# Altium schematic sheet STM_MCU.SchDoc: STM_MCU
size A3; Author: J. Garnier; DrawnBy: J. Garnier; SheetNumber: 2; SheetTotal: 8
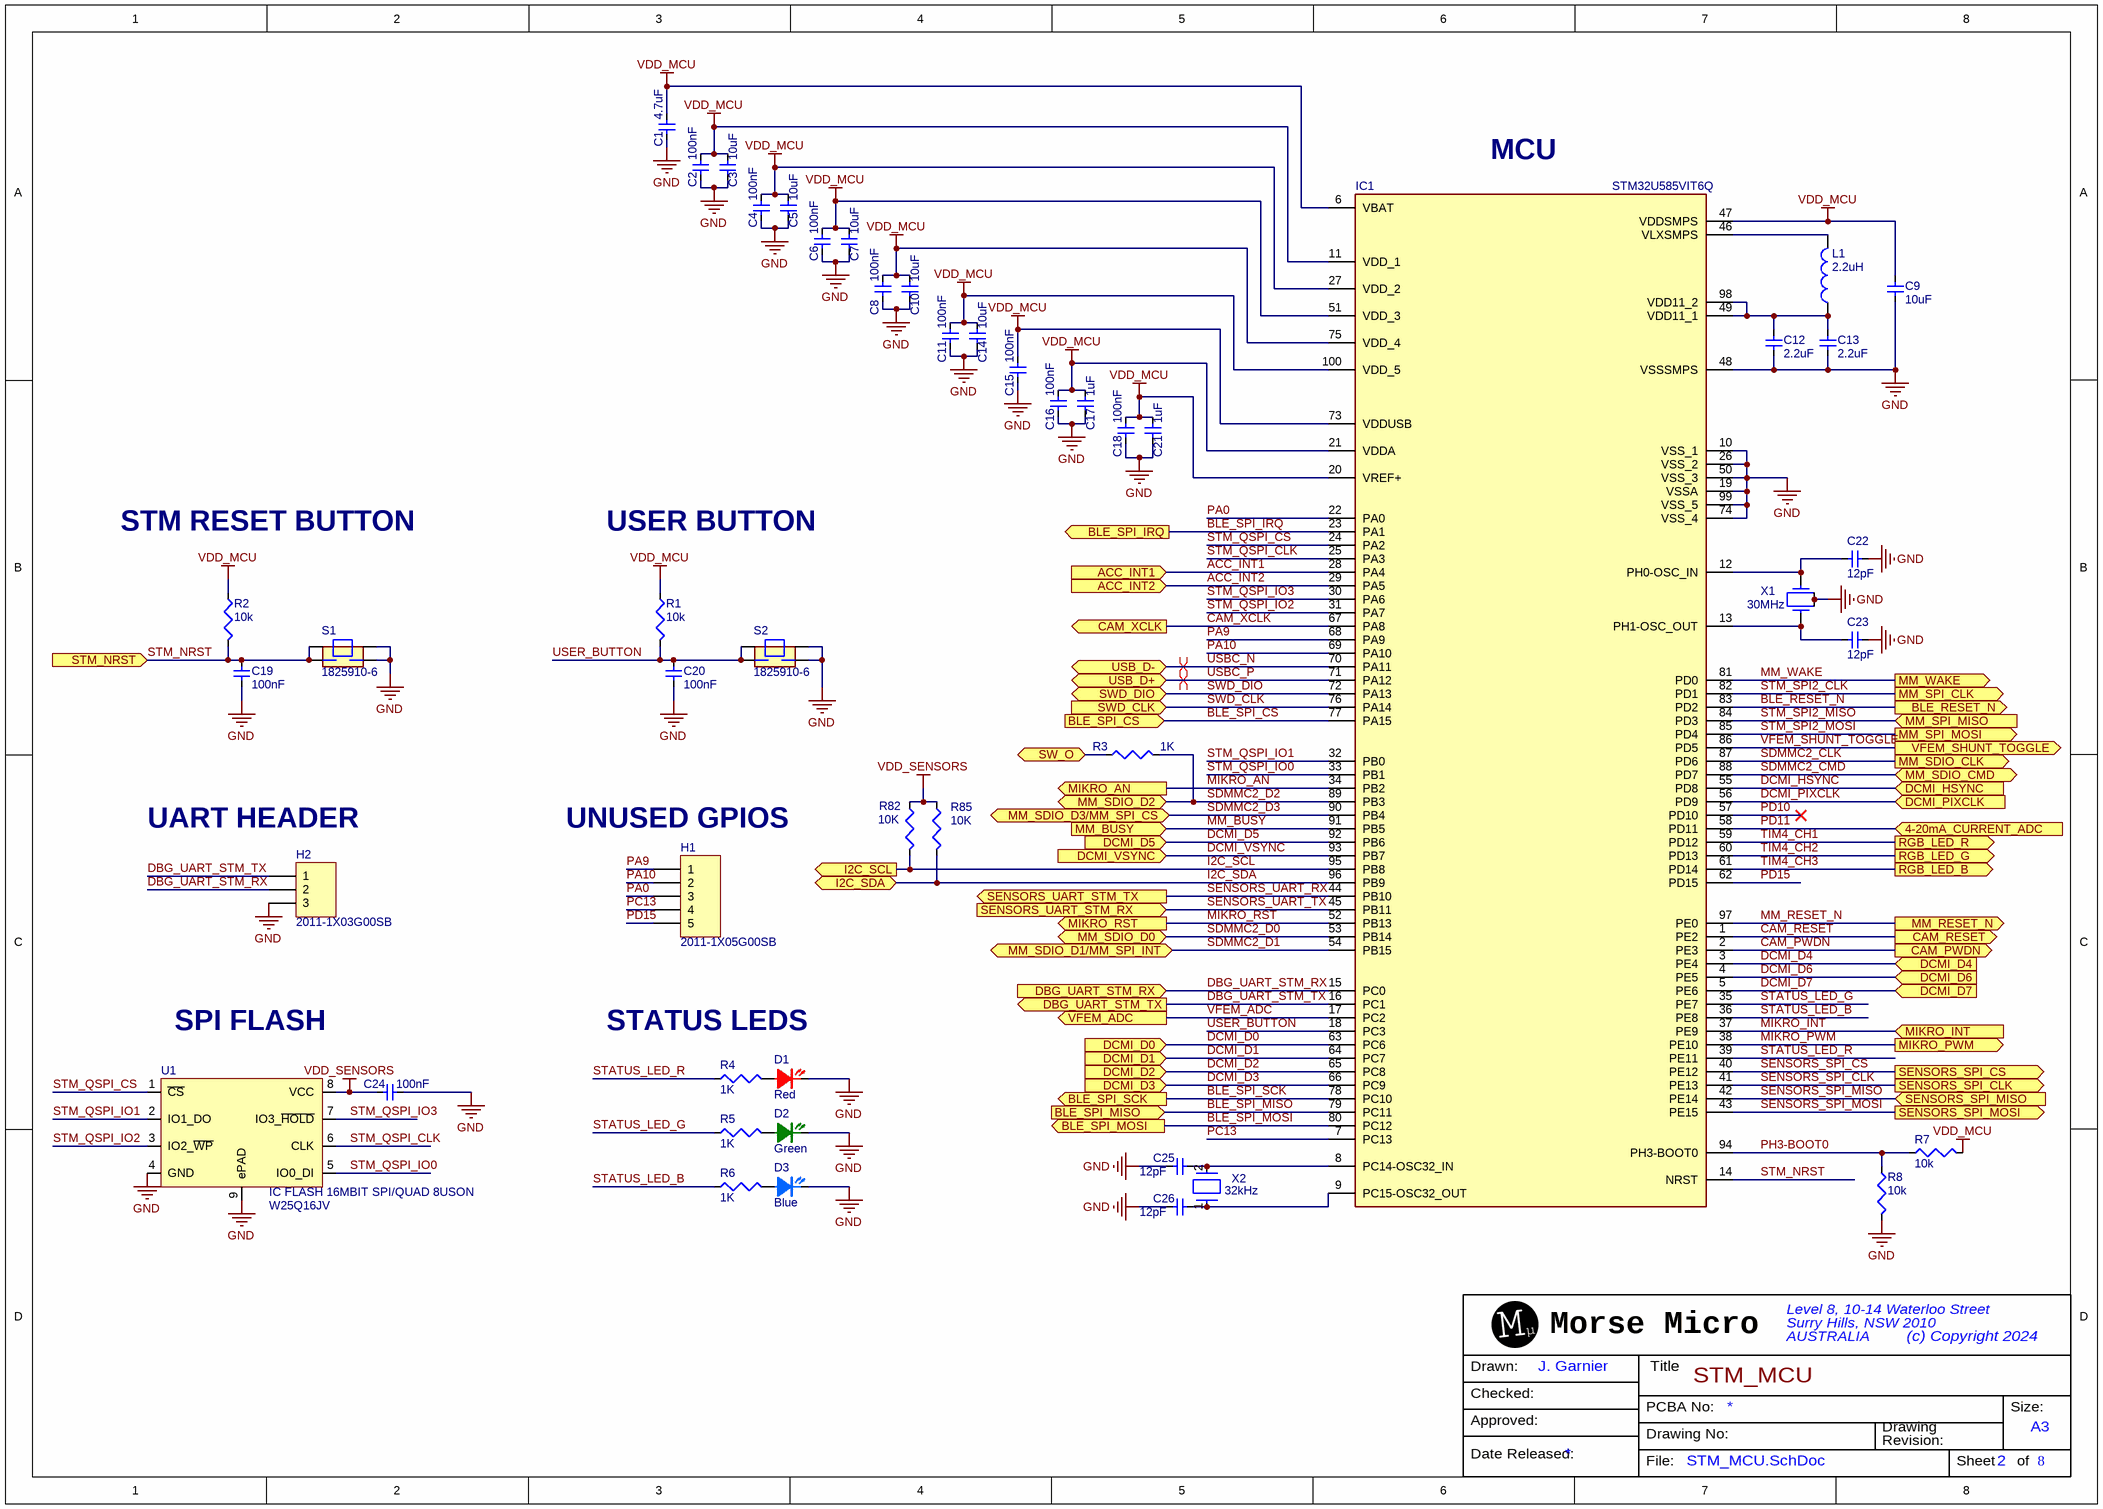
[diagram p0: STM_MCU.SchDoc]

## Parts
C1  value 4.7uF  [0402_cap]  (hidden comment: GRM155R61A475MEAAD)
C2  value 100nF  [0402_cap]  (hidden comment: C1005X7R1H104K050BE)
C3  value 10uF  [0402_cap]  (hidden comment: CL05A106MP8NUB8)
C4  value 100nF  [0402_cap]  (hidden comment: C1005X7R1H104K050BE)
C5  value 10uF  [0402_cap]  (hidden comment: CL05A106MP8NUB8)
C6  value 100nF  [0402_cap]  (hidden comment: C1005X7R1H104K050BE)
C7  value 10uF  [0402_cap]  (hidden comment: CL05A106MP8NUB8)
C8  value 100nF  [0402_cap]  (hidden comment: C1005X7R1H104K050BE)
C9  value 10uF  [0402_cap]  (hidden comment: CL05A106MP8NUB8)
C10  value 10uF  [0402_cap]  (hidden comment: CL05A106MP8NUB8)
C11  value 100nF  [0402_cap]  (hidden comment: C1005X7R1H104K050BE)
C12  value 2.2uF  [CAPC1005X06N]  (hidden comment: GRM155R61E225ME15D)
C13  value 2.2uF  [CAPC1005X06N]  (hidden comment: GRM155R61E225ME15D)
C14  value 10uF  [0402_cap]  (hidden comment: CL05A106MP8NUB8)
C15  value 100nF  [0402_cap]  (hidden comment: C1005X7R1H104K050BE)
C16  value 100nF  [0402_cap]  (hidden comment: C1005X7R1H104K050BE)
C17  value 1uF  [CAPC1005X06N]  (hidden comment: CL05A105KA5NQNC)
C18  value 100nF  [0402_cap]  (hidden comment: C1005X7R1H104K050BE)
C19  value 100nF  [CAPC1005X06N]  (hidden comment: LMK105BJ104KV-F)
C20  value 100nF  [CAPC1005X06N]  (hidden comment: LMK105BJ104KV-F)
C21  value 1uF  [CAPC1005X06N]  (hidden comment: CL05A105KA5NQNC)
C22  value 12pF  [CAPC0603X03N]  (hidden comment: GRM0335C1E120JA01D)
C23  value 12pF  [CAPC0603X03N]  (hidden comment: GRM0335C1E120JA01D)
C24  value 100nF  [CAPC0603X03N]  (hidden comment: CL03A104KQ3NNNC)
C25  value 12pF  [CAPC0603X03N]  (hidden comment: GRM0335C1E120JA01D)
C26  value 12pF  [CAPC0603X03N]  (hidden comment: GRM0335C1E120JA01D)
D1  value Red  [LED_0805_RED]  (hidden comment: LTST-C170KRKT)
D2  value Green  [LED_0805_GREEN]  (hidden comment: LTST-C170KGKT)
D3  value Blue  [LED_0805_BLUE]  (hidden comment: LTST-C170TBKT)
H1  2011-1X05G00SB  [HDR1X5 - Short Gold]
H2  2011-1X03G00SB  [HDR1X3]
IC1  STM32U585VIT6Q  [STM32U585VIT6]
L1  value 2.2uH  [INDC1608X10N]  (hidden comment: ASMPH-0603-2R2M-T)
R1  value 10k  [RESC1005X04N]  (hidden comment: MCR01MZPF1002)
R2  value 10k  [RESC1005X04N]  (hidden comment: MCR01MZPF1002)
R3  value 1K  [RESC1005X04N]  (hidden comment: ERJ-2RKF1001X)
R4  value 1K  [RESC1005X04N]  (hidden comment: ERJ-2RKF1001X)
R5  value 1K  [RESC1005X04N]  (hidden comment: ERJ-2RKF1001X)
R6  value 1K  [RESC1005X04N]  (hidden comment: ERJ-2RKF1001X)
R7  value 10k  [RESC1005X04N]  (hidden comment: MCR01MZPF1002)
R8  value 10k  [RESC1005X04N]  (hidden comment: MCR01MZPF1002)
R82  value 10K  [0402_res]  (hidden comment: ERJ-2RKF1002X)
R85  value 10K  [0402_res]  (hidden comment: ERJ-2RKF1002X)
S1  1825910-6  [TL1105]
S2  1825910-6  [TL1105]
U1  IC FLASH 16MBIT SPI/QUAD 8USON  value W25Q16JV  [USON8P20X30X6]
X1  value 30MHz  [XTAL_SMD_2016]  (hidden comment: ECS-300-10-37-CKM-TR)
X2  value 32kHz  [FP-ABS06-MFG]  (hidden comment: ABS06-107-32.768KHZ-T)

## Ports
4-20mA_CURRENT_ADC (in, see Main[3C], Sensors[7A]), ACC_INT1 (in, see Main[3C], Sensors[1B]), ACC_INT2 (in, see Main[3C], Sensors[1B]), BLE_RESET_N (out, see Main[2C], BLE_Module[2B]), BLE_SPI_CS (in, see Main[2C], BLE_Module[4B]), BLE_SPI_IRQ (out, see Main[2C], BLE_Module[4B]), BLE_SPI_MISO (in, see Main[2C], BLE_Module[4B]), BLE_SPI_MOSI (out, see Main[2C], BLE_Module[4B]), BLE_SPI_SCK (out, see Main[2C], BLE_Module[4A]), CAM_PWDN (out, see Main[3B], Sensors[7C]), CAM_RESET (out, see Main[3B], Sensors[5C]), CAM_XCLK (out, see Main[3B], Sensors[7C]), DBG_UART_STM_RX (in, see Main[2B]), DBG_UART_STM_TX (out, see Main[2B]), DCMI_D0 (in, see Main[3B]), DCMI_D1 (in, see Main[3B]), DCMI_D2 (in, see Main[3B]), DCMI_D3 (in, see Main[3C]), DCMI_D4 (in, see Main[3C]), DCMI_D5 (in, see Main[3C]), DCMI_D6 (in, see Main[3C]), DCMI_D7 (in, see Main[3C]), DCMI_HSYNC (in, see Main[3B]), DCMI_PIXCLK (in, see Main[3B]), DCMI_VSYNC (in, see Main[3B]), I2C_SCL (out, see Main[3A], Sensors[4A]), I2C_SDA (bidir, see Main[3A], Sensors[4A]), MIKRO_AN (out, see Main[3B], Sensors[5C]), MIKRO_INT (in, see Main[3B], Sensors[8C]), MIKRO_PWM (out, see Main[3A], Sensors[8C]), MIKRO_RST (out, see Main[3B], Sensors[5C]), MM_BUSY (in, see Main[2A], HaLow_Module[2A]), MM_RESET_N (out, see Main[2A], HaLow_Module[2B]), MM_SDIO_CLK (out, see Main[2A], HaLow_Module[1C]), MM_SDIO_CMD (bidir, see Main[2A], HaLow_Module[1C]), MM_SDIO_D0 (bidir, see Main[2A], HaLow_Module[1C]), MM_SDIO_D1/MM_SPI_INT (bidir, see Main[2A], HaLow_Module[1B]), MM_SDIO_D2 (bidir, see Main[2B], HaLow_Module[1B]), MM_SDIO_D3/MM_SPI_CS (bidir, see Main[2B], HaLow_Module[1B]), MM_SPI_CLK (out, see Main[2B], HaLow_Module[3C]), MM_SPI_MISO (in, see Main[2B], HaLow_Module[3C]), MM_SPI_MOSI (out, see Main[2B], HaLow_Module[3C]), MM_WAKE (out, see Main[2A], HaLow_Module[2B]), RGB_LED_B (out, see Main[3A], Sensors[2D]), RGB_LED_G (out, see Main[3A], Sensors[2D]), RGB_LED_R (out, see Main[3A], Sensors[3D]), SENSORS_SPI_CLK (out, see Main[3B]), SENSORS_SPI_CS (out, see Main[3B], Sensors[5C]), SENSORS_SPI_MISO (in, see Main[3B], Sensors[5D]), SENSORS_SPI_MOSI (out, see Main[3B], Sensors[5D]), SENSORS_UART_STM_RX (in, see Main[3B]), SENSORS_UART_STM_TX (out, see Main[3B]), STM_NRST (in, see Main[2B], Power[1B]), SW_O (bidir, see Main[2B], Power[1B]), SWD_CLK (in, see Main[2B], Power[1B]), SWD_DIO (bidir, see Main[2B], Power[1B]), USB_D+ (bidir, see Main[2B], Power[4A]), USB_D- (bidir, see Main[2B], Power[4A]), VFEM_ADC (out, see Main[2B], Power[5D]), VFEM_SHUNT_TOGGLE (out, see Main[2C], Power[4D])

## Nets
GND: C1.1 C2.1 C3.1 C4.1 C5.1 C6.1 C7.1 C8.1 C9.2 C10.1 C11.1 C12.2 C13.2 C14.1 C15.1 C16.1 C17.1 C18.1 C19.2 C20.2 C21.1 C22.2 C23.2 C24.1 C25.1 C26.1 D1.K D2.K D3.K H2.3 IC1.10(VSS_1) IC1.19(VSSA) IC1.26(VSS_2) IC1.48(VSSSMPS) IC1.50(VSS_3) IC1.74(VSS_4) IC1.99(VSS_5) R8.2 S1.3 S1.4 S2.3 S2.4 U1.4(GND) U1.9(ePAD) X1.2 X1.4
VDD_MCU: C1.2 C2.2 C3.2 C4.2 C5.2 C6.2 C7.2 C8.2 C9.1 C10.2 C11.2 C14.2 C15.2 C16.2 C17.2 C18.2 C21.2 IC1.6(VBAT) IC1.11(VDD_1) IC1.20(VREF+) IC1.21(VDDA) IC1.27(VDD_2) IC1.47(VDDSMPS) IC1.51(VDD_3) IC1.73(VDDUSB) IC1.75(VDD_4) IC1.100(VDD_5) R1.1 R2.1 R7.2
VDD_SENSORS: C24.2 R82.1 R85.1 U1.8(VCC)
ACC_INT1: IC1.28(PA4) ; port ACC_INT1
ACC_INT2: IC1.29(PA5) ; port ACC_INT2
BLE_RESET_N: IC1.83(PD2) ; port BLE_RESET_N
BLE_SPI_CS: IC1.77(PA15) ; port BLE_SPI_CS
BLE_SPI_IRQ: IC1.23(PA1) ; port BLE_SPI_IRQ
BLE_SPI_MISO: IC1.79(PC11) ; port BLE_SPI_MISO
BLE_SPI_MOSI: IC1.80(PC12) ; port BLE_SPI_MOSI
BLE_SPI_SCK: IC1.78(PC10) ; port BLE_SPI_SCK
CAM_PWDN: IC1.2(PE3) ; port CAM_PWDN
CAM_RESET: IC1.1(PE2) ; port CAM_RESET
CAM_XCLK: IC1.67(PA8) ; port CAM_XCLK
DBG_UART_STM_RX: H2.2 IC1.15(PC0) ; port DBG_UART_STM_RX
DBG_UART_STM_TX: H2.1 IC1.16(PC1) ; port DBG_UART_STM_TX
DCMI_D0: IC1.63(PC6) ; port DCMI_D0
DCMI_D1: IC1.64(PC7) ; port DCMI_D1
DCMI_D2: IC1.65(PC8) ; port DCMI_D2
DCMI_D3: IC1.66(PC9) ; port DCMI_D3
DCMI_D4: IC1.3(PE4) ; port DCMI_D4
DCMI_D5: IC1.92(PB6) ; port DCMI_D5
DCMI_D6: IC1.4(PE5) ; port DCMI_D6
DCMI_D7: IC1.5(PE6) ; port DCMI_D7
DCMI_HSYNC: IC1.55(PD8) ; port DCMI_HSYNC
DCMI_PIXCLK: IC1.56(PD9) ; port DCMI_PIXCLK
DCMI_VSYNC: IC1.93(PB7) ; port DCMI_VSYNC
I2C_SCL: IC1.95(PB8) R82.2 ; port I2C_SCL
I2C_SDA: IC1.96(PB9) R85.2 ; port I2C_SDA
MIKRO_AN: IC1.34(PB2) ; port MIKRO_AN
MIKRO_INT: IC1.37(PE9) ; port MIKRO_INT
MIKRO_PWM: IC1.38(PE10) ; port MIKRO_PWM
MIKRO_RST: IC1.52(PB13) ; port MIKRO_RST
MM_BUSY: IC1.91(PB5) ; port MM_BUSY
MM_RESET_N: IC1.97(PE0) ; port MM_RESET_N
MM_WAKE: IC1.81(PD0) ; port MM_WAKE
PA0: H1.3 IC1.22(PA0)
PA9: H1.1 IC1.68(PA9)
PA10: H1.2 IC1.69(PA10)
PC13: H1.4 IC1.7(PC13)
PD10: IC1.57(PD10)
PD11: IC1.58(PD11) ; port 4-20mA_CURRENT_ADC
PD15: H1.5 IC1.62(PD15)
PH3-BOOT0: IC1.94(PH3-BOOT0) R7.1 R8.1
SDMMC2_CLK: IC1.87(PD6) ; port MM_SDIO_CLK
SDMMC2_CMD: IC1.88(PD7) ; port MM_SDIO_CMD
SDMMC2_D0: IC1.53(PB14) ; port MM_SDIO_D0
SDMMC2_D1: IC1.54(PB15) ; port MM_SDIO_D1/MM_SPI_INT
SDMMC2_D2: IC1.89(PB3) R3.2 ; port MM_SDIO_D2
SDMMC2_D3: IC1.90(PB4) ; port MM_SDIO_D3/MM_SPI_CS
SENSORS_SPI_CLK: IC1.41(PE13) ; port SENSORS_SPI_CLK
SENSORS_SPI_CS: IC1.40(PE12) ; port SENSORS_SPI_CS
SENSORS_SPI_MISO: IC1.42(PE14) ; port SENSORS_SPI_MISO
SENSORS_SPI_MOSI: IC1.43(PE15) ; port SENSORS_SPI_MOSI
SENSORS_UART_RX: IC1.44(PB10) ; port SENSORS_UART_STM_TX
SENSORS_UART_TX: IC1.45(PB11) ; port SENSORS_UART_STM_RX
STATUS_LED_B: IC1.36(PE8) R6.1
STATUS_LED_G: IC1.35(PE7) R5.1
STATUS_LED_R: IC1.39(PE11) R4.1
STM_NRST: C19.1 IC1.14(NRST) R2.2 S1.1 S1.2 ; port STM_NRST
STM_QSPI_CLK: IC1.25(PA3) U1.6(CLK)
STM_QSPI_CS: IC1.24(PA2) U1.1(~{CS})
STM_QSPI_IO0: IC1.33(PB1) U1.5(IO0_DI)
STM_QSPI_IO1: IC1.32(PB0) U1.2(IO1_DO)
STM_QSPI_IO2: IC1.31(PA7) U1.3(IO2_~{WP})
STM_QSPI_IO3: IC1.30(PA6) U1.7(IO3_~{HOLD})
STM_SPI2_CLK: IC1.82(PD1) ; port MM_SPI_CLK
STM_SPI2_MISO: IC1.84(PD3) ; port MM_SPI_MISO
STM_SPI2_MOSI: IC1.85(PD4) ; port MM_SPI_MOSI
SW_O: R3.1 ; port SW_O
SWD_CLK: IC1.76(PA14) ; port SWD_CLK
SWD_DIO: IC1.72(PA13) ; port SWD_DIO
TIM4_CH1: IC1.59(PD12) ; port RGB_LED_R
TIM4_CH2: IC1.60(PD13) ; port RGB_LED_G
TIM4_CH3: IC1.61(PD14) ; port RGB_LED_B
USBC_N: IC1.70(PA11) ; port USB_D-
USBC_P: IC1.71(PA12) ; port USB_D+
USER_BUTTON: C20.1 IC1.18(PC3) R1.2 S2.1 S2.2
VFEM_ADC: IC1.17(PC2) ; port VFEM_ADC
VFEM_SHUNT_TOGGLE: IC1.86(PD5) ; port VFEM_SHUNT_TOGGLE
NetC12_1: C12.1 C13.1 IC1.49(VDD11_1) IC1.98(VDD11_2) L1.1
NetC22_1: C22.1 IC1.12(PH0-OSC_IN) X1.3
NetC23_1: C23.1 IC1.13(PH1-OSC_OUT) X1.1
NetC25_2: C25.2 IC1.8(PC14-OSC32_IN) X2.2
NetC26_2: C26.2 IC1.9(PC15-OSC32_OUT) X2.1
NetD1_A: D1.A R4.2
NetD2_A: D2.A R5.2
NetD3_A: D3.A R6.2
NetIC1_46: IC1.46(VLXSMPS) L1.2

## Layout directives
differential pair: USBC_N, USBC_P

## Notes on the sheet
- (near IC1) MCU
- STM RESET BUTTON
- USER BUTTON
- (near H2) UART HEADER
- (near H1) UNUSED GPIOS
- SPI FLASH
- STATUS LEDS

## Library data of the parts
C1 = CAP0157-11: CAP CER 4.7UF 10V ±20% X5R 0402; Subtype: Ceramic; Generic Allowed: Yes
C2 C4 C6 C8 C11 C15 C16 C18 = CAP0068-11: CAP CER 100NF 50V ±10% X7R 0402; Subtype: Ceramic; Generic Allowed: Yes
C3 C5 C7 C9 C10 C14 = CAP0046-13: CAP CER 10UF 10V 20% X5R 0402; Generic Allowed: Yes; Subtype: Ceramic
C12 C13 = CAP0055-10: CAP CER 2.2UF 25V ±20% X5R 0402; Subtype: Ceramic; Generic Allowed: Yes
C17 C21 = CAP0168-10: CAP CER 1UF 25V ±10% X5R 0402; Generic Allowed: Yes; Subtype: Ceramic
C19 C20 = CAP0196-10: CAP CER 100NF 10V ±10% X5R 0402; Generic Allowed: Yes; Subtype: Ceramic
C22 C23 C25 C26 = CAP0010-6: CAP CER 12PF 25V ±5% C0G/NP0 0201; Subtype: Ceramic; Generic Allowed: Yes; Component Rating: C0G, NPO
C24 = CAP0134-6: CAP CER 100NF 6.3V ±10% X5R 0201; Subtype: Ceramic; Generic Allowed: Yes
D1 = DIO0016-2: LED, Red Clear,2.0V, SMD, 0805, RoHS; Generic Allowed: Yes
D2 = DIO0015-2: LED, Green Clear,2.0V, SMD, 0805, RoHS; Generic Allowed: Yes
D3 = DIO0018-2: LED, Blue Clear,3.3V, SMD, 0805, RoHS; Generic Allowed: Yes
H1 = HDR0119-2: 2011 Series Single Row 5 Position 2.54 mm 3 A Straight Gold Flash Pin Header
H2 = HDR0008-2: Conn Straight Header 3x1 0.100" 3 POS; Generic Allowed: Yes
IC1 = ICT0224-2: Generic Allowed: No
L1 = IND0038-5: INDUCTOR 2.2UH 10% 0603 SMD; Generic Allowed: Yes; Tolerance: 20%; Current: 300mA; Resistance: 300mOhm; Frequency: 80MHz
R1 R2 R7 R8 = RES0043-8: RES SMD 10K OHM ±1% 1/16W 0402; Generic Allowed: Yes
R3-R6 = RES0004-8: RES SMD 1K OHM ±1% 1/10W 0402; Generic Allowed: Yes
R82 R85 = RES0002-9: RES SMD 10K OHM ±1% 1/10W 0402; Generic Allowed: Yes
S1 S2 = SWH0038-1: Keypad Switch, 1 Switches, SPST, Momentary-tactile, 0.05A, 24VDC, 2.06N, 4 PCB Hole Cnt, Solder Terminal, Through Hole-straight; Body Height: 3.61mm; Body Length or Diameter: 5.99mm; Body Breadth: 5.99inch; Contact DC Max Rating R Load: .05A@24VDC; Contact Current(DC)-Max: 50mA; Circuit Configuration: 1X1; Electrical Life: 100000Cycles; Number of Switches: 1; Contact Voltage(DC)-Max: 24V
U1 = ICT0220-1: Generic Allowed: No
X1 = OSC0002-3: OSC XTAL 30MHZ 10PF 10PPM SMD2016; Generic Allowed: No
X2 = OSC0044-1: Parallel - Fundamental Quartz Crystal, 0.032768MHz Nom; Frequency Stability: 0.025%; Additional Feature: TAPE AND REEL; Drive Level: 0.1uW; ESR: 80kR; Aging: 3 PPM/FIRST YEAR; Frequency Tolerance: 20ppm; Load Capacitance: 4pF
